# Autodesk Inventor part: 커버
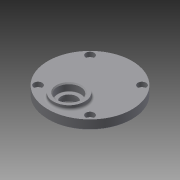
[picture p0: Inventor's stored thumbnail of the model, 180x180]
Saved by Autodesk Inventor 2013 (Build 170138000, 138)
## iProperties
Created: 2015-07
Part Number: 커버
Material: 일반
Document SubType Name: Modeling
Designer: user
Density: 1 g/cm^3
Author: user
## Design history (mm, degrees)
sketch "스케치1"
  geometry: C1 r 40 at (0, 0); 1 further point
  constraints: 1 centre point, 1 coincident
  dimensions: "d0" = 40 radius of C1
extrude "돌출1" new body sketch "스케치1" distance "d1" = 9; taper "d2" = 0 deg
sketch "스케치2"
  geometry: L1 (0, 0)-(0, -20); C1 r 40 at (0, 0) reference; C2 r 15 at (0, -20)
  constraints: 2 end point, 1 centre point, 1 coincident, 1 vertical
  dimensions: "d3" = 20 distance of L1.start L1.end; "d4" = 15 radius of C2
extrude "돌출2" join sketch "스케치2" distance "d5" = 4; taper "d6" = 0 deg
sketch "스케치3"
  geometry: C1 r 15 at (0, 0) reference; C2 r 11 at (0, 0); 1 further point
  constraints: 1 centre point, 1 coincident
  dimensions: "d7" = 11 radius of C2
extrude "돌출3" cut sketch "스케치3" distance "d8" = 7; taper "d9" = 0 deg
sketch "스케치4"
  geometry: L1 (0, 0)-(0, 11); L2 (0, 0)-(0, -20); C1 r 40 at (0, 0) reference; C2 r 14 at (0, 11); C3 r 14 at (0, -20)
  constraints: 4 end point, 2 centre point, 2 coincident, 1 collinear, 1 vertical
  dimensions: "d10" = 11 distance of L1.start L1.end; "d11" = 14 radius of C2; "d12" = 20 distance of L1.start L2.end; "d13" = 14 radius of C3
extrude "돌출4" join sketch "스케치4" distance "d14" = 3; taper "d15" = 0 deg
sketch "스케치5"
  geometry: C1 r 14 at (0, 0) reference; C2 r 11 at (0, 0); 1 further point
  constraints: 1 centre point, 1 coincident
  dimensions: "d16" = 11 radius of C2
extrude "돌출5" cut sketch "스케치5" distance "d17" = 7; taper "d18" = 0 deg
sketch "스케치6"
  geometry: C1 r 11 at (0, 0) reference; C2 r 7.5 at (0, 0); 1 further point
  constraints: 1 centre point, 1 coincident
  dimensions: "d19" = 7.5 radius of C2
extrude "돌출6" cut sketch "스케치6" distance "d20" = 2; taper "d21" = 0 deg
sketch "스케치7"
  geometry: C1 r 14 at (0, 0) reference; C2 r 11 at (0, 0); 1 further point
  constraints: 1 centre point, 1 coincident
  dimensions: "d22" = 11 radius of C2
extrude "돌출7" cut sketch "스케치7" distance "d23" = 7; taper "d24" = 0 deg
sketch "스케치8"
  geometry: C1 r 9 at (0, 0); 2 further points
  constraints: 1 centre point, 1 coincident, 1 vertical alignment
  dimensions: "d25" = 9 radius of C1
extrude "돌출8" cut sketch "스케치8" distance "d26" = 1; taper "d27" = 0 deg
chamfer "모따기1" distance "d28" = 1; stored, may be unused: second distance "d29" = 2, angle "d30" = 45 deg
chamfer "모따기2" distance "d31" = 1; stored, may be unused: second distance "d32" = 2, angle "d33" = 45 deg
fillet "모깎기1" dims "d34" = 0.3
sketch "스케치9"
  geometry: L1 (0, 0)-(0, 35); L2 (0, 0)-(24.749, 24.749); C1 r 40 at (0, 0) reference; A1 r 35 centre (0, 0) between (0, 35) and (24.749, 24.749)
  constraints: 4 end point, 2 point on circle, 1 centre point, 1 coincident, 1 vertical
  dimensions: "d35" = 35 radius of A1; "d36" = 45 deg angle of L2 L1
hole "구멍1" sketch "스케치9" at (24.749, 24.749) diameter "d38" = 4.5; stored, may be unused: countersink angle "d42" = 90 deg, drill point angle "d44" = 118 deg; dims "d39" = 6, "d40" = 8, "d41" = 4.4, "d43" = 8
fillet "모깎기2" dims "d48" = 2
node "솔리드1"
pattern_circular "원형 패턴1" dims angle "d46" = 360 deg
